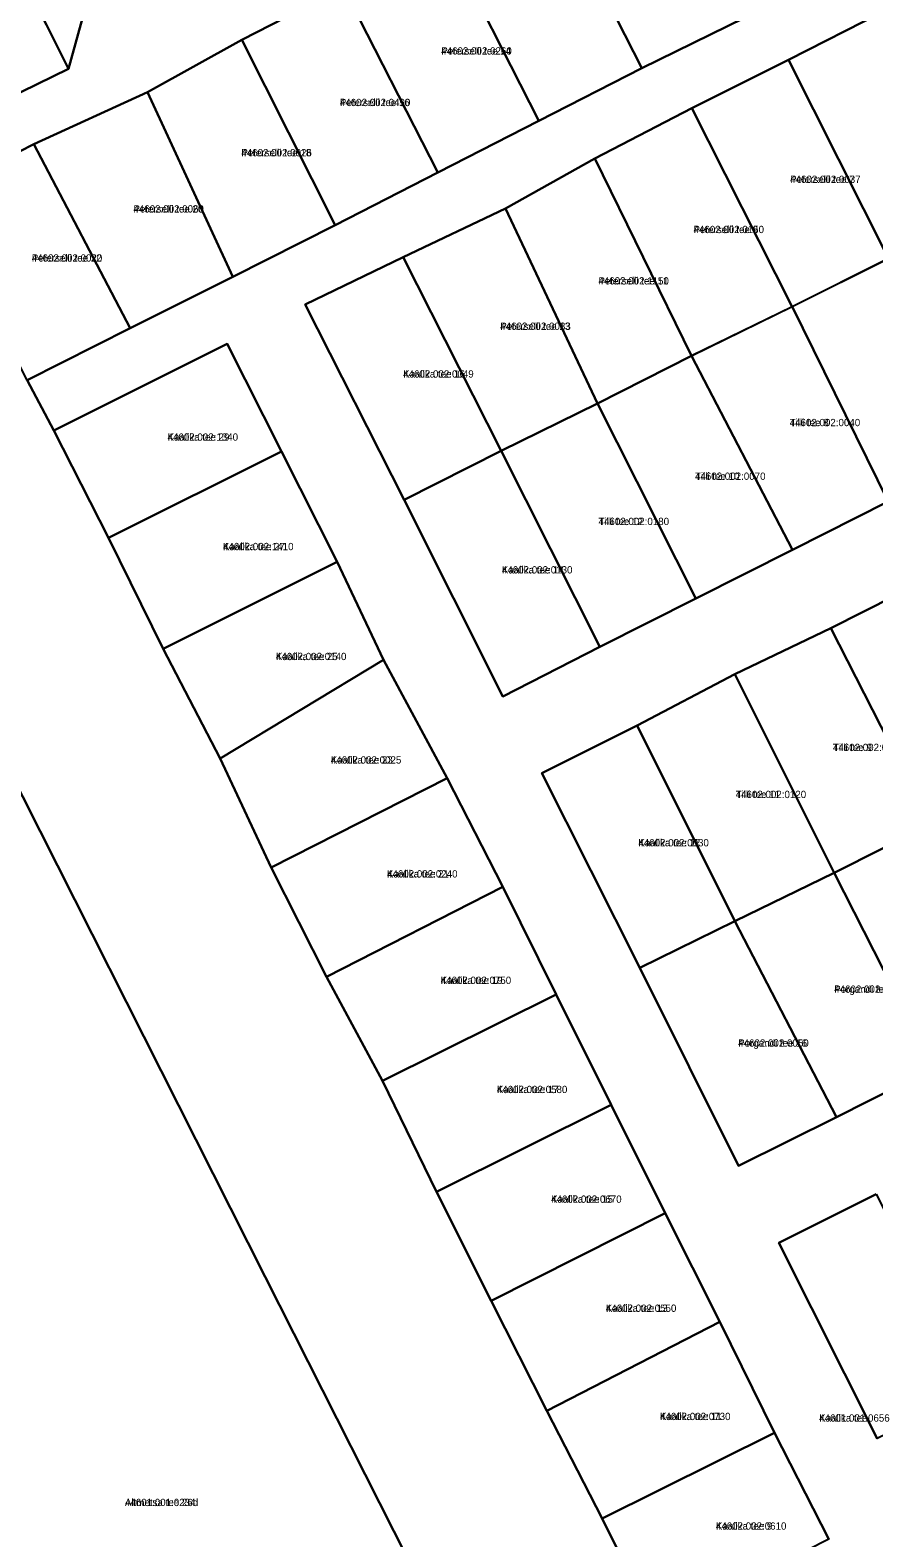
# Model space of a CAD drawing. Extents: x 551843 to 558501, y 6589003 to 6595718.
# Drawn here: x 554722.9 to 554896.4, y 6592596.3 to 6592906.2 of the extents above; entities that cross this region are included whole.
import ezdxf

# ---------------------------------------------------------------- set-up
doc = ezdxf.new("R2010")
doc.units = 0
for name, color, linetype in [('L_AADRESS', 7, 'Continuous'), ('PIIR', 7, 'Continuous'), ('TUNNUS', 7, 'Continuous')]:
    doc.layers.add(name, color=color, linetype=linetype)

msp = doc.modelspace()

# ---------------------------------------------------------------- linework, layer by layer
at = {"layer": 'PIIR'}
for points in [[(554923.69, 6592347.53), (554878.41, 6592438.09), (554841.8, 6592510.41), (554771.18, 6592649.95), (554642.95, 6592903.73), (554573.43, 6593041.09), (554529.22, 6593128.57), (554464.48, 6593256.08), (554446.62, 6593289.09), (554441.09, 6593299.31), (554261.19, 6593527.78)], [(554705.77, 6592962.91), (554723.11, 6592931.04), (554734.19, 6592910.64), (554730.76, 6592898.25), (554726.23, 6592907.32), (554712.86, 6592933.09)], [(554787.31, 6592915), (554766.39, 6592904.21), (554746.98, 6592893.48), (554723.65, 6592882.76), (554702.95, 6592872.25)], [(554701.82, 6592884.15), (554730.76, 6592898.25), (554734.19, 6592910.64)], [(554898.19, 6592909.95), (554878.78, 6592900.13), (554858.94, 6592890.16), (554838.96, 6592879.84), (554820.59, 6592869.55), (554799.54, 6592859.57), (554779.4, 6592849.81), (554799.78, 6592809.65), (554820.07, 6592769.2), (554839.98, 6592779.47), (554859.75, 6592789.37), (554879.63, 6592799.39), (554899.28, 6592809.31)], [(554887.11, 6592596.02), (554875.92, 6592617.88), (554864.69, 6592640.69), (554853.48, 6592663.05), (554842.33, 6592685.28), (554831.06, 6592708), (554820.03, 6592730.09), (554808.6, 6592752.43), (554795.5, 6592776.77), (554786.01, 6592796.94), (554774.55, 6592819.57), (554763.39, 6592841.76), (554727.72, 6592823.94), (554722.28, 6592834.27), (554743.42, 6592844.96), (554764.52, 6592855.53), (554785.59, 6592866.1), (554806.71, 6592876.98), (554827.49, 6592887.54), (554848.65, 6592898.38), (554869.77, 6592908.72)], [(554722.28, 6592834.27), (554727.72, 6592823.94), (554738.99, 6592801.85), (554750.2, 6592779.05), (554761.91, 6592756.47), (554772.4, 6592734.1), (554783.79, 6592711.6), (554795.32, 6592690.19), (554806.42, 6592667.4), (554817.67, 6592645.02), (554829.12, 6592622.4), (554840.48, 6592600.26), (554851.57, 6592578.01), (554862.78, 6592556.14), (554874.23, 6592533.28), (554884.52, 6592510.22), (554895.63, 6592487.75), (554899.6, 6592481.94), (554935.47, 6592406.31), (554931.19, 6592404.15), (554948.61, 6592369.7), (554959.44, 6592348.28)], [(554907.45, 6592793.36), (554887.5, 6592783.3), (554867.79, 6592773.85), (554847.66, 6592763.29), (554828.11, 6592753.44), (554848.25, 6592713.44), (554868.5, 6592672.74), (554888.68, 6592682.72), (554908.65, 6592692.84)], [(554896.85, 6592666.95), (554876.81, 6592656.9), (554897.07, 6592616.68)]]:
    msp.add_lwpolyline(points, dxfattribs=at)
for points in [[(554848.65, 6592898.38), (554829.51, 6592935.96), (554850.91, 6592946.84), (554869.77, 6592908.72)], [(554827.49, 6592887.54), (554808.22, 6592925.47), (554829.51, 6592935.96), (554848.65, 6592898.38)], [(554697.11, 6592892.89), (554684.09, 6592919.15), (554712.86, 6592933.09), (554726.23, 6592907.32), (554730.76, 6592898.25), (554701.82, 6592884.15)], [(554806.71, 6592876.98), (554787.31, 6592915), (554808.22, 6592925.47), (554827.49, 6592887.54)], [(554785.59, 6592866.1), (554766.39, 6592904.21), (554787.31, 6592915), (554806.71, 6592876.98)], [(554899.34, 6592859.3), (554878.78, 6592900.13), (554898.19, 6592909.95), (554919.11, 6592869.18)], [(554745.26, 6592499.11), (554711.7, 6592493.45), (554704.16, 6592538.17), (554673.19, 6592719.82), (554646.24, 6592883.65), (554642.93, 6592903.77), (554771.18, 6592649.95), (554841.8, 6592510.41), (554768.62, 6592501.84)], [(554766.39, 6592904.21), (554785.59, 6592866.1), (554764.52, 6592855.53), (554746.98, 6592893.48)], [(554858.94, 6592890.16), (554878.78, 6592900.13), (554899.34, 6592859.3), (554879.57, 6592849.36)], [(554743.42, 6592844.96), (554723.65, 6592882.76), (554746.98, 6592893.48), (554764.52, 6592855.53)], [(554858.83, 6592839.26), (554838.96, 6592879.84), (554858.94, 6592890.16), (554879.57, 6592849.36)], [(554722.28, 6592834.27), (554702.95, 6592872.25), (554723.65, 6592882.76), (554743.42, 6592844.96)], [(554839.52, 6592829.45), (554820.59, 6592869.55), (554838.96, 6592879.84), (554858.83, 6592839.26)], [(554799.54, 6592859.57), (554820.59, 6592869.55), (554839.52, 6592829.45), (554819.74, 6592819.74)], [(554779.4, 6592849.81), (554799.54, 6592859.57), (554819.74, 6592819.74), (554799.78, 6592809.65)], [(554879.59, 6592849.37), (554899.34, 6592859.3), (554919.22, 6592819.36), (554899.28, 6592809.31)], [(554879.59, 6592849.37), (554899.28, 6592809.31), (554879.63, 6592799.39), (554858.83, 6592839.26)], [(554763.39, 6592841.76), (554774.55, 6592819.57), (554738.99, 6592801.85), (554727.72, 6592823.94)], [(554858.83, 6592839.26), (554879.63, 6592799.39), (554859.75, 6592789.37), (554839.52, 6592829.45)], [(554839.52, 6592829.45), (554859.75, 6592789.37), (554839.98, 6592779.47), (554819.74, 6592819.74)], [(554738.99, 6592801.85), (554774.55, 6592819.57), (554786.01, 6592796.94), (554750.2, 6592779.05)], [(554819.74, 6592819.74), (554839.98, 6592779.47), (554820.07, 6592769.2), (554799.78, 6592809.65)], [(554750.2, 6592779.05), (554786.01, 6592796.94), (554795.5, 6592776.77), (554761.91, 6592756.47)], [(554907.45, 6592793.36), (554927.67, 6592753.11), (554908.09, 6592742.97), (554887.5, 6592783.3)], [(554867.79, 6592773.85), (554887.5, 6592783.3), (554908.09, 6592742.97), (554888.23, 6592733)], [(554795.5, 6592776.77), (554808.6, 6592752.43), (554772.4, 6592734.1), (554761.91, 6592756.47)], [(554847.66, 6592763.29), (554867.79, 6592773.85), (554888.23, 6592733), (554867.74, 6592723.07)], [(554828.11, 6592753.44), (554847.66, 6592763.29), (554867.74, 6592723.07), (554848.25, 6592713.44)], [(554783.79, 6592711.6), (554772.4, 6592734.1), (554808.6, 6592752.43), (554820.03, 6592730.09)], [(554908.09, 6592742.97), (554928.17, 6592702.94), (554908.65, 6592692.84), (554888.23, 6592733)], [(554888.23, 6592733), (554908.65, 6592692.84), (554888.68, 6592682.72), (554867.74, 6592723.07)], [(554783.79, 6592711.6), (554820.03, 6592730.09), (554831.06, 6592708), (554795.32, 6592690.19)], [(554867.74, 6592723.07), (554888.68, 6592682.72), (554868.5, 6592672.74), (554848.25, 6592713.44)], [(554831.06, 6592708), (554842.33, 6592685.28), (554806.42, 6592667.4), (554795.32, 6592690.19)], [(554842.33, 6592685.28), (554853.48, 6592663.05), (554817.67, 6592645.02), (554806.42, 6592667.4)], [(554896.85, 6592666.95), (554917.21, 6592626.51), (554897.07, 6592616.68), (554876.81, 6592656.9)], [(554817.67, 6592645.02), (554853.48, 6592663.05), (554864.69, 6592640.69), (554829.12, 6592622.4)], [(554864.69, 6592640.69), (554875.92, 6592617.88), (554840.48, 6592600.26), (554829.12, 6592622.4)], [(554875.92, 6592617.88), (554887.11, 6592596.02), (554851.57, 6592578.01), (554840.48, 6592600.26)]]:
    msp.add_lwpolyline(points, close=True, dxfattribs=at)

# ---------------------------------------------------------------- texts
at = {"layer": 'L_AADRESS'}
for s, p in [('Peterselli tee 14', (554807.4, 6592901.2)), ('Peterselli tee 16', (554786.55, 6592890.6)), ('Peterselli tee 18', (554766.29, 6592880.28)), ('Peterselli tee 7', (554879.14, 6592874.81)), ('Peterselli tee 20', (554744.09, 6592868.72)), ('Peterselli tee 9', (554859.27, 6592864.49)), ('Peterselli tee 22', (554723.19, 6592858.63)), ('Peterselli tee 11', (554839.71, 6592853.93)), ('Peterselli tee 13', (554819.53, 6592844.6)), ('Kaalika tee 16', (554799.57, 6592834.79)), ('Tilli tee 8', (554879.05, 6592824.8)), ('Kaalika tee 29', (554751.12, 6592821.81)), ('Tilli tee 10', (554859.58, 6592813.77)), ('Tilli tee 12', (554839.75, 6592804.47)), ('Kaalika tee 27', (554762.52, 6592799.31)), ('Kaalika tee 14', (554819.88, 6592794.52)), ('Kaalika tee 25', (554773.4, 6592776.71)), ('Kaalika tee 23', (554784.69, 6592755.44)), ('Tilli tee 9', (554887.94, 6592758.01)), ('Tilli tee 11', (554867.94, 6592748.35)), ('Kaalika tee 12', (554847.93, 6592738.42)), ('Kaalika tee 21', (554796.25, 6592732.02)), ('Kaalika tee 19', (554807.28, 6592710.14)), ('Porgandi tee 14', (554888.2, 6592708.32)), ('Porgandi tee 16', (554868.46, 6592697.24)), ('Kaalika tee 17', (554818.83, 6592687.7)), ('Kaalika tee 15', (554829.99, 6592665.15)), ('Kaalika tee 13', (554841.25, 6592642.73)), ('Kaalika tee 11', (554852.38, 6592620.48)), ('Kaalika tee', (554885.12, 6592620.16)), ('Altmetsa tee 26d', (554742.36, 6592602.8)), ('Kaalika tee 9', (554863.88, 6592597.95))]:
    msp.add_text(s, height=1.5, dxfattribs=at).set_placement(p)
at = {"layer": 'TUNNUS'}
for s, p in [('44602:002:0260', (554807.4, 6592901.2)), ('44602:002:0490', (554786.55, 6592890.6)), ('44602:002:0026', (554766.29, 6592880.28)), ('44602:002:0037', (554879.14, 6592874.81)), ('44602:002:0060', (554744.09, 6592868.72)), ('44602:002:0150', (554859.27, 6592864.49)), ('44602:002:0020', (554723.19, 6592858.63)), ('44602:002:1150', (554839.71, 6592853.93)), ('44602:002:0033', (554819.53, 6592844.6)), ('44602:002:0049', (554799.57, 6592834.79)), ('44602:002:0040', (554879.05, 6592824.8)), ('44602:002:1340', (554751.12, 6592821.81)), ('44602:002:0070', (554859.58, 6592813.77)), ('44602:002:0180', (554839.75, 6592804.47)), ('44602:002:1410', (554762.52, 6592799.31)), ('44602:002:0130', (554819.88, 6592794.52)), ('44602:002:0140', (554773.4, 6592776.71)), ('44602:002:0025', (554784.69, 6592755.44)), ('44602:002:0110', (554887.94, 6592758.01)), ('44602:002:0120', (554867.94, 6592748.35)), ('44602:002:0030', (554847.93, 6592738.42)), ('44602:002:0240', (554796.25, 6592732.02)), ('44602:002:0750', (554807.28, 6592710.14)), ('44602:002:0760', (554888.2, 6592708.32)), ('44602:002:0050', (554868.46, 6592697.24)), ('44602:002:0580', (554818.83, 6592687.7)), ('44602:002:0670', (554829.99, 6592665.15)), ('44602:002:0550', (554841.25, 6592642.73)), ('44602:002:0730', (554852.38, 6592620.48)), ('44601:001:0656', (554885.12, 6592620.16)), ('44601:001:0234', (554742.36, 6592602.8)), ('44602:002:0610', (554863.88, 6592597.95))]:
    msp.add_text(s, height=1.5, dxfattribs=at).set_placement(p)

doc.saveas('drawing.dxf')
